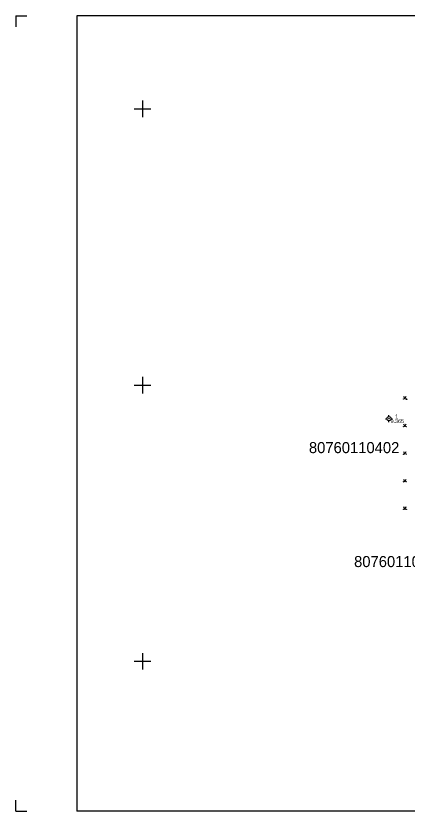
# Model space of a CAD drawing. Extents: x 496127 to 496334, y 303823 to 303967.
# Drawn here: x 496127.1 to 496197.9, y 303822.9 to 303966.8 of the extents above; entities that cross this region are included whole.
import ezdxf

# ---------------------------------------------------------------- set-up
doc = ezdxf.new("R2010")
doc.units = 0
for name, color, linetype in [('GEOD_ELEM_####_####_#', 7, 'Continuous'), ('GEOD_ELEM_####_TKST_#', 7, 'Continuous'), ('Level 59', 7, 'Continuous'), ('RAMI_PLAN_####_TKST_#', 7, 'Continuous'), ('RELJ_ELEM_####_####_#', 7, 'Continuous'), ('TERT_ELEM_####_####_#', 7, 'Continuous')]:
    doc.layers.add(name, color=color, linetype=linetype)

msp = doc.modelspace()

# ---------------------------------------------------------------- linework, layer by layer
at = {"layer": 'GEOD_ELEM_####_####_#'}
for p, q in [((496150, 303951.5), (496150, 303950)), ((496148.5, 303950), (496150, 303950)), ((496150, 303950), (496150, 303948.5)), ((496150, 303950), (496151.5, 303950)), ((496150, 303901.5), (496150, 303900)), ((496148.5, 303900), (496150, 303900)), ((496150, 303900), (496150, 303898.5)), ((496150, 303900), (496151.5, 303900)), ((496193.99, 303893.92), (496194.24, 303893.92)), ((496194.62, 303894.3), (496194.62, 303894.55)), ((496194.62, 303893.3), (496194.62, 303893.55)), ((496194.99, 303893.92), (496195.24, 303893.92)), ((496150, 303851.5), (496150, 303850)), ((496148.5, 303850), (496150, 303850)), ((496150, 303850), (496150, 303848.5)), ((496150, 303850), (496151.5, 303850))]:
    msp.add_line(p, q, dxfattribs=at)
for radius in [0.375, 0.05]:
    msp.add_circle((496194.62, 303893.92), radius, dxfattribs=at)
at = {"layer": 'RAMI_PLAN_####_TKST_#'}
for p, q in [((496127.1, 303966.84), (496127.1, 303964.84)), ((496127.1, 303966.84), (496129.1, 303966.84)), ((496138.1, 303966.84), (496138.1, 303822.89)), ((496334.1, 303966.84), (496138.1, 303966.84)), ((496127.1, 303822.89), (496127.1, 303824.89)), ((496127.1, 303822.89), (496129.1, 303822.89)), ((496334.1, 303822.89), (496138.1, 303822.89))]:
    msp.add_line(p, q, dxfattribs=at)
at = {"layer": 'RELJ_ELEM_####_####_#'}
msp.add_circle((496197.8, 303897.45), 0.05, dxfattribs=at)
at = {"layer": 'TERT_ELEM_####_####_#'}
for p, q in [((496197.25, 303898), (496197.5, 303897.5)), ((496197.5, 303897.5), (496197.75, 303898)), ((496197.25, 303893), (496197.5, 303892.5)), ((496197.5, 303892.5), (496197.75, 303893)), ((496197.25, 303888), (496197.5, 303887.5)), ((496197.5, 303887.5), (496197.75, 303888)), ((496197.25, 303883), (496197.5, 303882.5)), ((496197.5, 303882.5), (496197.75, 303883)), ((496197.25, 303878), (496197.5, 303877.5)), ((496197.5, 303877.5), (496197.75, 303878))]:
    msp.add_line(p, q, dxfattribs=at)
for centre, radius in [((496197.25, 303897.5), 0.028), ((496197.75, 303897.5), 0.0263), ((496197.25, 303892.5), 0.028), ((496197.75, 303892.5), 0.0263), ((496197.25, 303887.5), 0.028), ((496197.75, 303887.5), 0.0263), ((496197.25, 303882.5), 0.028), ((496197.75, 303882.5), 0.0263), ((496197.25, 303877.5), 0.028), ((496197.75, 303877.5), 0.0263)]:
    msp.add_circle(centre, radius, dxfattribs=at)

# ---------------------------------------------------------------- texts
at = {"layer": 'GEOD_ELEM_####_TKST_#'}
for s, p in [(' 1', (496195.49, 303893.99)), (' 9.365', (496194.65, 303893.13))]:
    msp.add_text(s, height=0.7, dxfattribs=at).set_placement(p)
at = {"layer": 'Level 59'}
for s, p in [('80760110402', (496180.13, 303887.69)), ('80760110084', (496188.3, 303867.06))]:
    msp.add_text(s, height=2, dxfattribs=at).set_placement(p)

doc.saveas('drawing.dxf')
